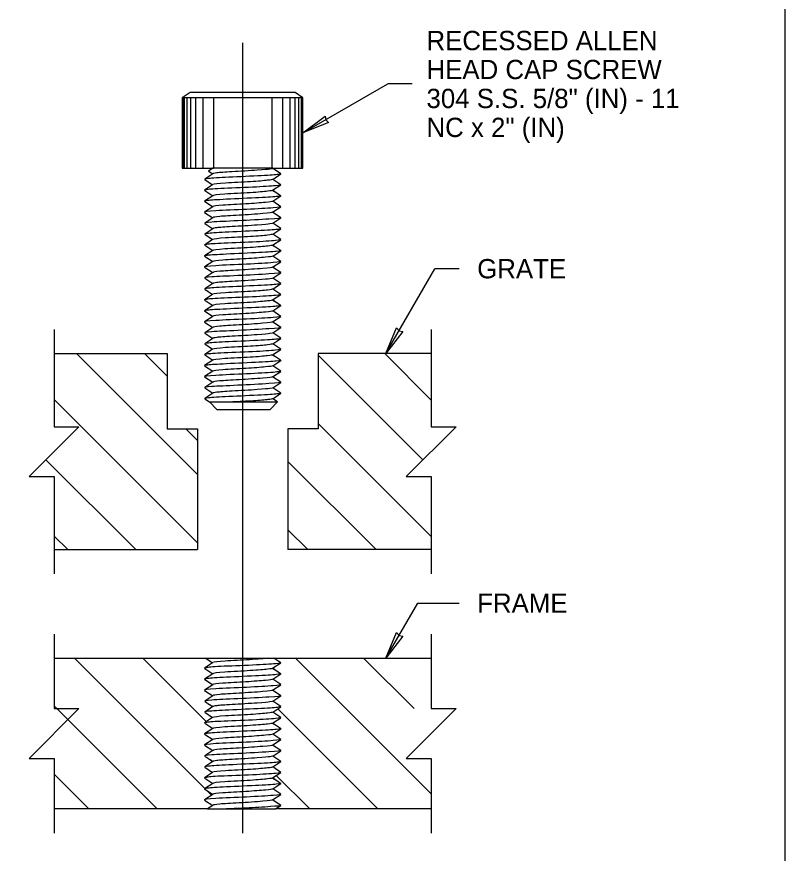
# Model space of a CAD drawing. Extents: x 99862 to 103151, y 100000 to 102076.
# Drawn here: x 102514 to 103151, y 100926 to 101620 of the extents above; entities that cross this region are included whole.
import ezdxf

# ---------------------------------------------------------------- set-up
doc = ezdxf.new("R2010")
doc.units = 0
for name, color, linetype in [('Level 1', 7, 'Continuous'), ('Level 14', 7, 'Continuous'), ('Level 15', 7, 'Continuous'), ('Level 17', 7, 'Continuous'), ('Level 2', 7, 'Continuous'), ('Level 20', 7, 'Continuous')]:
    doc.layers.add(name, color=color, linetype=linetype)

msp = doc.modelspace()

# ---------------------------------------------------------------- linework, layer by layer
at = {"layer": 'Level 1'}
for p, q in [((102670.78, 101087.88), (102676.47, 101084.06)), ((102732.89, 101084.12), (102727.28, 101087.88)), ((102676.47, 101084.06), (102669.79, 101079.63)), ((102669.95, 101079.39), (102676.5, 101075)), ((102726.16, 101079.5), (102732.89, 101083.97)), ((102732.83, 101075.02), (102726.16, 101079.5)), ((102676.5, 101075), (102669.83, 101070.59)), ((102726.23, 101070.41), (102732.89, 101074.81)), ((102669.83, 101070.37), (102676.53, 101065.88)), ((102676.53, 101065.88), (102669.83, 101061.42)), ((102726.17, 101061.28), (102732.89, 101065.79)), ((102732.89, 101065.93), (102726.23, 101070.41)), ((102669.83, 101061.21), (102676.5, 101056.73)), ((102732.89, 101056.77), (102726.17, 101061.28)), ((102676.5, 101056.73), (102669.89, 101052.33)), ((102726.28, 101052.19), (102732.89, 101056.62)), ((102732.89, 101047.75), (102726.28, 101052.19)), ((102676.53, 101047.7), (102669.89, 101043.24)), ((102726.22, 101043.13), (102732.89, 101047.61)), ((102676.47, 101038.61), (102669.79, 101034.17)), ((102669.89, 101043.02), (102676.47, 101038.61)), ((102726.16, 101034.04), (102732.89, 101038.52)), ((102732.89, 101038.66), (102726.22, 101043.13)), ((102669.95, 101033.93), (102676.5, 101029.54)), ((102732.83, 101029.57), (102726.16, 101034.04)), ((102676.5, 101029.54), (102669.83, 101025.13)), ((102669.83, 101024.92), (102676.53, 101020.42)), ((102726.23, 101024.95), (102732.89, 101029.35)), ((102732.89, 101020.48), (102726.23, 101024.95)), ((102676.53, 101020.42), (102669.83, 101015.97)), ((102726.17, 101015.82), (102732.89, 101020.33)), ((102669.83, 101015.75), (102676.5, 101011.27)), ((102676.5, 101011.27), (102669.89, 101006.88)), ((102732.89, 101011.32), (102726.17, 101015.82)), ((102726.28, 101006.73), (102732.89, 101011.17)), ((102732.89, 101002.3), (102726.28, 101006.73)), ((102676.53, 101002.24), (102669.89, 100997.79)), ((102669.89, 100997.57), (102676.47, 100993.16)), ((102726.22, 100997.68), (102732.89, 101002.15)), ((102732.89, 100993.21), (102726.22, 100997.68)), ((102676.47, 100993.16), (102669.79, 100988.72)), ((102726.16, 100988.59), (102732.89, 100993.06)), ((102676.5, 100984.09), (102669.83, 100979.68)), ((102669.95, 100988.48), (102676.5, 100984.09)), ((102732.83, 100984.12), (102726.16, 100988.59)), ((102726.23, 100979.5), (102732.89, 100983.9)), ((102669.83, 100979.46), (102676.53, 100974.97)), ((102676.53, 100974.97), (102669.83, 100970.52)), ((102732.89, 100975.02), (102726.23, 100979.5)), ((102669.83, 100970.3), (102676.5, 100965.82)), ((102726.17, 100970.37), (102732.89, 100974.88)), ((102732.89, 100965.86), (102726.17, 100970.37)), ((102676.5, 100965.82), (102672.08, 100962.88)), ((102728.67, 100962.88), (102732.89, 100965.72))]:
    msp.add_line(p, q, dxfattribs=at)
msp.add_lwpolyline([(99862, 99999.5), (103151, 99999.5), (103151, 102075.5), (99862, 102075.5)], close=True, dxfattribs=at)
for points in [[(102669.89, 101052.12), (102671.6, 101050.95), (102672.23, 101050.59)], [(102672.48, 101050.37), (102676.53, 101047.7)], [(102669.89, 101006.66), (102671.6, 101005.5), (102672.23, 101005.13)], [(102672.48, 101004.92), (102676.53, 101002.24)]]:
    msp.add_lwpolyline(points, dxfattribs=at)
at = {"layer": 'Level 14'}
for p, q in [((102657.91, 101556.63), (102651.33, 101552.22)), ((102751.33, 101552.22), (102651.33, 101552.22)), ((102651.72, 101552.22), (102651.72, 101494.13)), ((102652.92, 101552.22), (102652.92, 101494.13)), ((102654.98, 101552.22), (102654.98, 101494.13)), ((102658.03, 101552.22), (102658.03, 101494.13)), ((102662.3, 101552.22), (102662.3, 101494.13)), ((102668.26, 101552.22), (102668.26, 101494.13)), ((102677.12, 101552.22), (102677.12, 101494.13)), ((102725.53, 101552.22), (102725.53, 101494.13)), ((102734.4, 101552.22), (102734.4, 101494.13)), ((102740.36, 101552.22), (102740.36, 101494.13)), ((102744.63, 101552.22), (102744.63, 101494.13)), ((102751.33, 101552.22), (102744.75, 101556.63)), ((102747.68, 101552.22), (102747.68, 101494.13)), ((102749.74, 101552.22), (102749.74, 101494.13)), ((102750.94, 101552.22), (102750.94, 101494.13)), ((102676.53, 101489.32), (102669.89, 101484.86)), ((102676.53, 101493.95), (102673.05, 101491.62)), ((102726.06, 101493.95), (102676.53, 101493.95)), ((102732.89, 101489.37), (102726.06, 101493.95)), ((102726.22, 101484.75), (102732.89, 101489.23)), ((102669.89, 101484.64), (102676.47, 101480.23)), ((102732.89, 101480.28), (102726.22, 101484.75)), ((102676.47, 101480.23), (102669.76, 101475.77)), ((102669.95, 101475.55), (102676.5, 101471.16)), ((102726.16, 101475.66), (102732.89, 101480.13)), ((102732.83, 101471.19), (102726.16, 101475.66)), ((102676.5, 101471.16), (102669.83, 101466.75)), ((102726.23, 101466.57), (102732.89, 101470.97)), ((102669.83, 101466.53), (102676.53, 101462.04)), ((102676.53, 101462.04), (102669.83, 101457.59)), ((102726.17, 101457.44), (102732.89, 101461.95)), ((102732.89, 101462.1), (102726.23, 101466.57)), ((102669.83, 101457.37), (102676.5, 101452.89)), ((102732.89, 101452.93), (102726.17, 101457.44)), ((102676.5, 101452.89), (102669.89, 101448.5)), ((102726.28, 101448.35), (102732.89, 101452.79)), ((102732.89, 101443.92), (102726.28, 101448.35)), ((102676.53, 101443.86), (102669.89, 101439.41)), ((102726.22, 101439.3), (102732.89, 101443.77)), ((102676.47, 101434.77), (102669.76, 101430.32)), ((102669.89, 101439.19), (102676.47, 101434.77)), ((102726.16, 101430.21), (102732.89, 101434.68)), ((102732.89, 101434.83), (102726.22, 101439.3)), ((102676.5, 101425.7), (102669.83, 101421.3)), ((102669.95, 101430.1), (102676.5, 101425.7)), ((102732.83, 101425.73), (102726.16, 101430.21)), ((102669.83, 101421.08), (102676.53, 101416.59)), ((102726.23, 101421.12), (102732.89, 101425.52)), ((102732.89, 101416.64), (102726.23, 101421.12)), ((102676.53, 101416.59), (102669.83, 101412.13)), ((102669.83, 101411.92), (102676.5, 101407.44)), ((102726.17, 101411.99), (102732.89, 101416.5)), ((102732.89, 101407.48), (102726.17, 101411.99)), ((102676.5, 101407.44), (102669.89, 101403.04)), ((102726.28, 101402.9), (102732.89, 101407.33)), ((102676.53, 101398.41), (102669.89, 101393.95)), ((102726.22, 101393.84), (102732.89, 101398.32)), ((102732.89, 101398.46), (102726.28, 101402.9)), ((102669.89, 101393.73), (102676.47, 101389.32)), ((102732.89, 101389.37), (102726.22, 101393.84)), ((102676.47, 101389.32), (102669.76, 101384.86)), ((102669.95, 101384.64), (102676.5, 101380.25)), ((102726.16, 101384.75), (102732.89, 101389.23)), ((102732.83, 101380.28), (102726.16, 101384.75)), ((102676.5, 101380.25), (102669.83, 101375.84)), ((102726.23, 101375.66), (102732.89, 101380.06)), ((102669.83, 101375.63), (102676.53, 101371.13)), ((102676.53, 101371.13), (102669.83, 101366.68)), ((102726.17, 101366.53), (102732.89, 101371.04)), ((102732.89, 101371.19), (102726.23, 101375.66)), ((102669.83, 101366.46), (102676.5, 101361.98)), ((102732.89, 101362.03), (102726.17, 101366.53)), ((102676.5, 101361.98), (102669.89, 101357.59)), ((102726.28, 101357.44), (102732.89, 101361.88)), ((102732.89, 101353.01), (102726.28, 101357.44)), ((102676.53, 101352.95), (102669.89, 101348.5)), ((102726.22, 101348.39), (102732.89, 101352.86)), ((102676.47, 101343.87), (102669.76, 101339.41)), ((102669.89, 101348.28), (102676.47, 101343.87)), ((102726.16, 101339.3), (102732.89, 101343.77)), ((102732.89, 101343.92), (102726.22, 101348.39)), ((102669.95, 101339.19), (102676.5, 101334.8)), ((102732.83, 101334.83), (102726.16, 101339.3)), ((102676.5, 101334.8), (102669.83, 101330.39)), ((102669.83, 101330.17), (102676.53, 101325.68)), ((102726.23, 101330.21), (102732.89, 101334.61)), ((102732.89, 101325.73), (102726.23, 101330.21)), ((102676.53, 101325.68), (102669.83, 101321.23)), ((102726.17, 101321.08), (102732.89, 101325.59)), ((102669.83, 101321.01), (102676.5, 101316.53)), ((102676.5, 101316.53), (102669.89, 101312.13)), ((102732.89, 101316.57), (102726.17, 101321.08)), ((102726.28, 101311.99), (102732.89, 101316.43)), ((102732.89, 101307.55), (102726.28, 101311.99)), ((102676.53, 101307.5), (102669.89, 101303.04)), ((102669.89, 101302.83), (102673.8, 101300.2)), ((102726.22, 101302.93), (102732.89, 101307.41)), ((102730.3, 101300.2), (102726.22, 101302.93)), ((102673.8, 101300.2), (102730.3, 101300.2)), ((102680.05, 101293.95), (102673.8, 101300.2)), ((102724.05, 101293.95), (102730.3, 101300.2)), ((102670.78, 101087.88), (102727.28, 101087.88)), ((102672.08, 100962.88), (102728.66, 100962.88))]:
    msp.add_line(p, q, dxfattribs=at)
for points in [[(102651.33, 101552.22), (102651.33, 101494.13), (102677.12, 101494.13)], [(102744.75, 101556.63), (102657.91, 101556.63)], [(102751.33, 101494.13), (102751.33, 101552.22)], [(102673.05, 101491.62), (102676.53, 101489.32)], [(102726.33, 101494.13), (102751.33, 101494.13)], [(102726.25, 101475.6), (102727.77, 101474.61)], [(102669.89, 101448.28), (102671.6, 101447.12), (102672.23, 101446.75), (102672.48, 101446.53), (102676.53, 101443.86)], [(102726.25, 101430.15), (102727.77, 101429.15)], [(102669.89, 101402.83), (102671.6, 101401.66), (102672.23, 101401.3), (102672.48, 101401.08), (102676.53, 101398.41)], [(102726.25, 101384.7), (102727.77, 101383.7)], [(102669.89, 101357.37), (102671.6, 101356.21), (102672.23, 101355.84), (102672.48, 101355.63), (102676.53, 101352.95)], [(102726.25, 101339.24), (102727.77, 101338.24)], [(102669.89, 101311.92), (102671.6, 101310.75), (102672.23, 101310.39), (102672.48, 101310.17), (102676.53, 101307.5)], [(102680.05, 101293.95), (102724.05, 101293.95)], [(102726.25, 101079.44), (102727.77, 101078.44)], [(102726.25, 101033.99), (102727.77, 101032.99)], [(102726.25, 100988.53), (102727.77, 100987.53)]]:
    msp.add_lwpolyline(points, dxfattribs=at)
for points in [[(102732.89, 101489.37), (102733.02, 101489.3), (102732.89, 101488.79), (102720.18, 101487.84), (102687.22, 101486.39), (102670.58, 101485.44), (102669.64, 101484.79), (102669.89, 101484.64)], [(102726.06, 101493.73), (102726.06, 101493.73), (102725.37, 101493.3), (102716.13, 101492.35), (102690.32, 101490.9), (102678.3, 101490.1), (102676.85, 101489.52), (102676.72, 101489.44)], [(102726, 101484.64), (102725.87, 101484.57), (102723.78, 101483.99), (102709.55, 101482.75), (102685.07, 101481.73), (102677.29, 101480.72), (102676.66, 101480.35)], [(102732.89, 101480.28), (102733.15, 101480.13), (102731.25, 101479.55), (102711.77, 101478.17), (102679.44, 101477.15), (102669.32, 101476.06), (102669.7, 101475.55), (102669.76, 101475.55)], [(102726, 101475.55), (102725.87, 101475.48), (102723.78, 101474.9), (102709.55, 101473.66), (102684.25, 101472.57), (102676.53, 101471.55), (102676.53, 101471.12)], [(102732.89, 101471.19), (102733.15, 101471.04), (102731.82, 101470.46), (102714.42, 101469.44), (102681.65, 101467.92), (102669.64, 101467.12), (102669.7, 101466.61), (102669.83, 101466.53)], [(102732.89, 101462.1), (102733.27, 101461.88), (102729.67, 101461.23), (102705.57, 101459.77), (102675.9, 101458.68), (102669.19, 101457.81), (102669.83, 101457.37)], [(102726, 101466.46), (102725.68, 101466.24), (102722.33, 101465.66), (102704.68, 101464.35), (102682.79, 101463.33), (102677.23, 101462.53), (102676.72, 101462.17)], [(102726.12, 101457.44), (102726.19, 101457.08), (102720.49, 101456.43), (102697.34, 101454.83), (102680.26, 101454.03), (102677.1, 101453.3), (102676.78, 101453.08)], [(102732.89, 101452.93), (102733.46, 101452.57), (102726.44, 101451.92), (102696.2, 101450.24), (102672.67, 101449.37), (102669.45, 101448.57), (102669.89, 101448.28)], [(102726.06, 101448.28), (102726.06, 101448.28), (102725.37, 101447.84), (102716.13, 101446.9), (102690.32, 101445.44), (102678.3, 101444.64), (102676.85, 101444.06), (102676.72, 101443.99)], [(102732.89, 101443.92), (102733.02, 101443.84), (102732.89, 101443.33), (102720.18, 101442.39), (102687.22, 101440.93), (102670.58, 101439.99), (102669.64, 101439.33), (102669.89, 101439.19)], [(102732.89, 101434.83), (102733.15, 101434.68), (102731.25, 101434.1), (102711.77, 101432.72), (102679.44, 101431.7), (102669.32, 101430.61), (102669.7, 101430.1), (102669.76, 101430.1)], [(102726, 101439.19), (102725.87, 101439.12), (102723.78, 101438.53), (102709.55, 101437.3), (102685.07, 101436.28), (102677.29, 101435.26), (102676.66, 101434.9)], [(102732.89, 101425.73), (102733.15, 101425.59), (102731.82, 101425.01), (102714.42, 101423.99), (102681.65, 101422.46), (102669.64, 101421.66), (102669.7, 101421.15), (102669.83, 101421.08)], [(102726, 101430.1), (102725.87, 101430.03), (102723.78, 101429.44), (102709.55, 101428.21), (102684.25, 101427.12), (102676.53, 101426.1), (102676.53, 101425.66)], [(102726, 101421.01), (102725.68, 101420.79), (102722.33, 101420.21), (102704.68, 101418.9), (102682.79, 101417.88), (102677.23, 101417.08), (102676.72, 101416.72)], [(102732.89, 101416.64), (102733.27, 101416.43), (102729.67, 101415.77), (102705.57, 101414.32), (102675.9, 101413.23), (102669.19, 101412.35), (102669.83, 101411.92)], [(102726.12, 101411.99), (102726.19, 101411.63), (102720.49, 101410.97), (102697.34, 101409.37), (102680.26, 101408.57), (102677.1, 101407.84), (102676.78, 101407.63)], [(102732.89, 101407.48), (102733.46, 101407.12), (102726.44, 101406.46), (102696.2, 101404.79), (102672.67, 101403.92), (102669.45, 101403.12), (102669.89, 101402.83)], [(102732.89, 101398.46), (102733.02, 101398.39), (102732.89, 101397.88), (102720.18, 101396.93), (102687.22, 101395.48), (102670.58, 101394.53), (102669.64, 101393.88), (102669.89, 101393.73)], [(102726.06, 101402.83), (102726.06, 101402.83), (102725.37, 101402.39), (102716.13, 101401.44), (102690.32, 101399.99), (102678.3, 101399.19), (102676.85, 101398.61), (102676.72, 101398.53)], [(102726, 101393.73), (102725.87, 101393.66), (102723.78, 101393.08), (102709.55, 101391.84), (102685.07, 101390.83), (102677.29, 101389.81), (102676.66, 101389.44)], [(102732.89, 101389.37), (102733.15, 101389.23), (102731.25, 101388.64), (102711.77, 101387.26), (102679.44, 101386.24), (102669.32, 101385.15), (102669.7, 101384.64), (102669.76, 101384.64)], [(102726, 101384.64), (102725.87, 101384.57), (102723.78, 101383.99), (102709.55, 101382.75), (102684.25, 101381.66), (102676.53, 101380.64), (102676.53, 101380.21)], [(102732.89, 101380.28), (102733.15, 101380.13), (102731.82, 101379.55), (102714.42, 101378.53), (102681.65, 101377.01), (102669.64, 101376.21), (102669.7, 101375.7), (102669.83, 101375.63)], [(102732.89, 101371.19), (102733.27, 101370.97), (102729.67, 101370.32), (102705.57, 101368.86), (102675.9, 101367.77), (102669.19, 101366.9), (102669.83, 101366.46)], [(102726, 101375.55), (102725.68, 101375.33), (102722.33, 101374.75), (102704.68, 101373.44), (102682.79, 101372.43), (102677.23, 101371.63), (102676.72, 101371.26)], [(102726.12, 101366.53), (102726.19, 101366.17), (102720.49, 101365.52), (102697.34, 101363.92), (102680.26, 101363.12), (102677.1, 101362.39), (102676.78, 101362.17)], [(102732.89, 101362.03), (102733.46, 101361.66), (102726.44, 101361.01), (102696.2, 101359.33), (102672.67, 101358.46), (102669.45, 101357.66), (102669.89, 101357.37)], [(102726.06, 101357.37), (102726.06, 101357.37), (102725.37, 101356.93), (102716.13, 101355.99), (102690.32, 101354.53), (102678.3, 101353.73), (102676.85, 101353.15), (102676.72, 101353.08)], [(102732.89, 101353.01), (102733.02, 101352.93), (102732.89, 101352.43), (102720.18, 101351.48), (102687.22, 101350.03), (102670.58, 101349.08), (102669.64, 101348.43), (102669.89, 101348.28)], [(102732.89, 101343.92), (102733.15, 101343.77), (102731.25, 101343.19), (102711.77, 101341.81), (102679.44, 101340.79), (102669.32, 101339.7), (102669.7, 101339.19), (102669.76, 101339.19)], [(102726, 101348.28), (102725.87, 101348.21), (102723.78, 101347.63), (102709.55, 101346.39), (102685.07, 101345.37), (102677.29, 101344.35), (102676.66, 101343.99)], [(102726, 101339.19), (102725.87, 101339.12), (102723.78, 101338.53), (102709.55, 101337.3), (102684.25, 101336.21), (102676.53, 101335.19), (102676.53, 101334.75)], [(102732.89, 101334.83), (102733.15, 101334.68), (102731.82, 101334.1), (102714.42, 101333.08), (102681.65, 101331.55), (102669.64, 101330.75), (102669.7, 101330.24), (102669.83, 101330.17)], [(102726, 101330.1), (102725.68, 101329.88), (102722.33, 101329.3), (102704.68, 101327.99), (102682.79, 101326.97), (102677.23, 101326.17), (102676.72, 101325.81)], [(102732.89, 101325.73), (102733.27, 101325.52), (102729.67, 101324.86), (102705.57, 101323.41), (102675.9, 101322.32), (102669.19, 101321.44), (102669.83, 101321.01)], [(102732.89, 101316.57), (102733.46, 101316.21), (102726.44, 101315.55), (102696.2, 101313.88), (102672.67, 101313.01), (102669.45, 101312.21), (102669.89, 101311.92)], [(102726.12, 101321.08), (102726.19, 101320.72), (102720.49, 101320.06), (102697.34, 101318.46), (102680.26, 101317.66), (102677.1, 101316.93), (102676.78, 101316.72)], [(102726.06, 101311.92), (102726.06, 101311.92), (102725.37, 101311.48), (102716.13, 101310.53), (102690.32, 101309.08), (102678.3, 101308.28), (102676.85, 101307.7), (102676.72, 101307.63)], [(102732.89, 101307.55), (102733.02, 101307.48), (102732.89, 101306.97), (102720.18, 101306.03), (102687.22, 101304.57), (102670.58, 101303.63), (102669.64, 101302.97), (102669.89, 101302.83)], [(102726, 101302.83), (102725.87, 101302.75), (102723.78, 101302.17), (102711.61, 101301.11), (102698.11, 101300.47), (102693.23, 101300.2)], [(102722.88, 101087.88), (102719.71, 101087.48), (102708.01, 101086.52), (102685.07, 101085.57), (102677.29, 101084.55), (102676.66, 101084.19)], [(102732.89, 101084.12), (102733.15, 101083.97), (102731.25, 101083.39), (102711.77, 101082.01), (102679.44, 101080.99), (102669.32, 101079.9), (102669.7, 101079.39), (102669.76, 101079.39)], [(102726, 101079.39), (102725.87, 101079.32), (102723.78, 101078.73), (102709.55, 101077.5), (102684.25, 101076.41), (102676.53, 101075.39), (102676.53, 101074.95)], [(102732.89, 101075.02), (102733.15, 101074.88), (102731.82, 101074.3), (102714.42, 101073.28), (102681.65, 101071.75), (102669.64, 101070.95), (102669.7, 101070.44), (102669.83, 101070.37)], [(102732.89, 101065.93), (102733.27, 101065.72), (102729.67, 101065.06), (102705.57, 101063.61), (102675.9, 101062.52), (102669.19, 101061.64), (102669.83, 101061.21)], [(102726, 101070.3), (102725.68, 101070.08), (102722.33, 101069.5), (102704.68, 101068.19), (102682.79, 101067.17), (102677.23, 101066.37), (102676.72, 101066.01)], [(102726.12, 101061.28), (102726.19, 101060.92), (102720.49, 101060.26), (102697.34, 101058.66), (102680.26, 101057.86), (102677.1, 101057.13), (102676.78, 101056.92)], [(102732.89, 101056.77), (102733.46, 101056.41), (102726.44, 101055.75), (102696.2, 101054.08), (102672.67, 101053.21), (102669.45, 101052.41), (102669.89, 101052.12)], [(102726.06, 101052.12), (102726.06, 101052.12), (102725.37, 101051.68), (102716.13, 101050.73), (102690.32, 101049.28), (102678.3, 101048.48), (102676.85, 101047.9), (102676.72, 101047.82)], [(102732.89, 101047.75), (102733.02, 101047.68), (102732.89, 101047.17), (102720.18, 101046.22), (102687.22, 101044.77), (102670.58, 101043.82), (102669.64, 101043.17), (102669.89, 101043.02)], [(102732.89, 101038.66), (102733.15, 101038.52), (102731.25, 101037.93), (102711.77, 101036.55), (102679.44, 101035.53), (102669.32, 101034.44), (102669.7, 101033.93), (102669.76, 101033.93)], [(102726, 101043.02), (102725.87, 101042.95), (102723.78, 101042.37), (102709.55, 101041.13), (102685.07, 101040.12), (102677.29, 101039.1), (102676.66, 101038.73)], [(102726, 101033.93), (102725.87, 101033.86), (102723.78, 101033.28), (102709.55, 101032.04), (102684.25, 101030.95), (102676.53, 101029.93), (102676.53, 101029.5)], [(102732.89, 101029.57), (102733.15, 101029.42), (102731.82, 101028.84), (102714.42, 101027.82), (102681.65, 101026.3), (102669.64, 101025.5), (102669.7, 101024.99), (102669.83, 101024.92)], [(102726, 101024.84), (102725.68, 101024.62), (102722.33, 101024.04), (102704.68, 101022.73), (102682.79, 101021.72), (102677.23, 101020.92), (102676.72, 101020.55)], [(102732.89, 101020.48), (102733.27, 101020.26), (102729.67, 101019.61), (102705.57, 101018.15), (102675.9, 101017.06), (102669.19, 101016.19), (102669.83, 101015.75)], [(102732.89, 101011.32), (102733.46, 101010.95), (102726.44, 101010.3), (102696.2, 101008.62), (102672.67, 101007.75), (102669.45, 101006.95), (102669.89, 101006.66)], [(102726.12, 101015.82), (102726.19, 101015.46), (102720.49, 101014.81), (102697.34, 101013.21), (102680.26, 101012.41), (102677.1, 101011.68), (102676.78, 101011.46)], [(102726.06, 101006.66), (102726.06, 101006.66), (102725.37, 101006.22), (102716.13, 101005.28), (102690.32, 101003.82), (102678.3, 101003.02), (102676.85, 101002.44), (102676.72, 101002.37)], [(102732.89, 101002.3), (102733.02, 101002.22), (102732.89, 101001.72), (102720.18, 101000.77), (102687.22, 100999.32), (102670.58, 100998.37), (102669.64, 100997.72), (102669.89, 100997.57)], [(102726, 100997.57), (102725.87, 100997.5), (102723.78, 100996.92), (102709.55, 100995.68), (102685.07, 100994.66), (102677.29, 100993.64), (102676.66, 100993.28)], [(102732.89, 100993.21), (102733.15, 100993.06), (102731.25, 100992.48), (102711.77, 100991.1), (102679.44, 100990.08), (102669.32, 100988.99), (102669.7, 100988.48), (102669.76, 100988.48)], [(102732.89, 100984.12), (102733.15, 100983.97), (102731.82, 100983.39), (102714.42, 100982.37), (102681.65, 100980.84), (102669.64, 100980.04), (102669.7, 100979.53), (102669.83, 100979.46)], [(102726, 100988.48), (102725.87, 100988.41), (102723.78, 100987.82), (102709.55, 100986.59), (102684.25, 100985.5), (102676.53, 100984.48), (102676.53, 100984.04)], [(102732.89, 100975.02), (102733.27, 100974.81), (102729.67, 100974.15), (102705.57, 100972.7), (102675.9, 100971.61), (102669.19, 100970.73), (102669.83, 100970.3)], [(102726, 100979.39), (102725.68, 100979.17), (102722.33, 100978.59), (102704.68, 100977.28), (102682.79, 100976.26), (102677.23, 100975.46), (102676.72, 100975.1)], [(102726.12, 100970.37), (102726.19, 100970.01), (102720.49, 100969.35), (102697.34, 100967.75), (102680.26, 100966.95), (102677.1, 100966.22), (102676.78, 100966.01)], [(102732.89, 100965.86), (102733.46, 100965.5), (102726.44, 100964.84), (102703.22, 100963.56), (102690.7, 100963.01), (102687.83, 100962.88)]]:
    msp.add_open_spline(points, degree=3, dxfattribs=at)
at = {"layer": 'Level 15'}
for p, q in [((102701.33, 101597.87), (102701.33, 100942.88)), ((102751.33, 101523.17), (102821.69, 101563.8)), ((102841.69, 101563.8), (102821.69, 101563.8)), ((102820.09, 101340.32), (102860.72, 101410.68)), ((102880.72, 101410.68), (102860.72, 101410.68)), ((102820.09, 101087.88), (102846.42, 101133.47)), ((102846.42, 101133.47), (102880.72, 101133.47))]:
    msp.add_line(p, q, dxfattribs=at)
for points in [[(102751.33, 101523.17), (102769.61, 101537.17), (102770.18, 101534.06), (102772.59, 101532)], [(102820.09, 101340.32), (102828.92, 101361.58), (102830.98, 101359.17), (102834.09, 101358.59)], [(102820.09, 101087.88), (102828.92, 101109.14), (102830.98, 101106.73), (102834.09, 101106.16)]]:
    msp.add_lwpolyline(points, close=True, dxfattribs=at)
for points in [[(102545.06, 101360.32), (102545.06, 101279.71), (102565.71, 101279.71), (102524.41, 101238.42), (102545.06, 101238.42), (102545.06, 101157.82)], [(102857.59, 101360.32), (102857.59, 101279.71), (102878.24, 101279.71), (102836.95, 101238.42), (102857.59, 101238.42), (102857.59, 101157.82)], [(102545.06, 101107.88), (102545.06, 101046.03), (102565.71, 101046.03), (102524.41, 101004.73), (102545.06, 101004.73), (102545.06, 100942.88)], [(102857.59, 101107.88), (102857.59, 101046.03), (102878.24, 101046.03), (102836.95, 101004.73), (102857.59, 101004.73), (102857.59, 100942.88)]]:
    msp.add_lwpolyline(points, dxfattribs=at)
at = {"layer": 'Level 17'}
for p, q in [((102663.83, 101240.05), (102563.56, 101340.32)), ((102638.83, 101321.62), (102620.13, 101340.32)), ((102850.68, 101252.15), (102763.83, 101339)), ((102857.59, 101301.8), (102819.08, 101340.32)), ((102663.83, 101183.48), (102545.06, 101302.25)), ((102857.59, 101188.67), (102763.83, 101282.43)), ((102663.83, 101268.33), (102654.35, 101277.82)), ((102612.92, 101177.82), (102538.37, 101252.37)), ((102811.88, 101177.82), (102738.83, 101250.87)), ((102755.31, 101177.82), (102738.83, 101194.3)), ((102556.36, 101177.82), (102545.06, 101189.11)), ((102562.01, 101087.88), (102670.1, 100979.79)), ((102618.58, 101087.88), (102671.39, 101035.07)), ((102745.04, 101087.88), (102857.59, 100975.33)), ((102801.61, 101087.88), (102843.46, 101046.03)), ((102545.06, 101048.26), (102630.45, 100962.88)), ((102730.41, 101045.94), (102813.48, 100962.88)), ((102674.35, 101003.83), (102676.18, 101001.99)), ((102545.06, 100991.7), (102573.88, 100962.88)), ((102729.23, 100990.56), (102756.91, 100962.88)), ((102671.48, 100978.41), (102675.59, 100974.31)), ((102545.06, 100963.41), (102545.59, 100962.88))]:
    msp.add_line(p, q, dxfattribs=at)
at = {"layer": 'Level 2'}
for p, q in [((102545.06, 101340.32), (102638.83, 101340.32)), ((102638.83, 101340.32), (102638.83, 101277.82)), ((102763.83, 101340.32), (102763.83, 101277.82)), ((102857.59, 101340.32), (102763.83, 101340.32)), ((102638.83, 101277.82), (102663.83, 101277.82)), ((102663.83, 101277.82), (102663.83, 101177.82)), ((102763.83, 101277.82), (102738.83, 101277.82)), ((102738.83, 101277.82), (102738.83, 101177.82)), ((102545.06, 101177.82), (102663.83, 101177.82)), ((102857.59, 101177.82), (102738.83, 101177.82)), ((102545.06, 101087.88), (102670.78, 101087.88)), ((102727.28, 101087.88), (102857.59, 101087.88)), ((102672.08, 100962.88), (102545.06, 100962.88)), ((102857.59, 100962.88), (102728.67, 100962.88))]:
    msp.add_line(p, q, dxfattribs=at)

# ---------------------------------------------------------------- texts
at = {"layer": 'Level 20'}
for s, p in [('RECESSED ALLEN', (102853.69, 101591.8)), ('HEAD CAP SCREW', (102853.69, 101567.8)), ('304 S.S. 5/8" (IN) - 11', (102853.69, 101543.8)), ('NC x 2" (IN)', (102853.69, 101519.8)), ('GRATE', (102895.71, 101402.69)), ('FRAME', (102895.71, 101125.47))]:
    msp.add_text(s, height=16, rotation=360, dxfattribs=at).set_placement(p)

doc.saveas('drawing.dxf')
